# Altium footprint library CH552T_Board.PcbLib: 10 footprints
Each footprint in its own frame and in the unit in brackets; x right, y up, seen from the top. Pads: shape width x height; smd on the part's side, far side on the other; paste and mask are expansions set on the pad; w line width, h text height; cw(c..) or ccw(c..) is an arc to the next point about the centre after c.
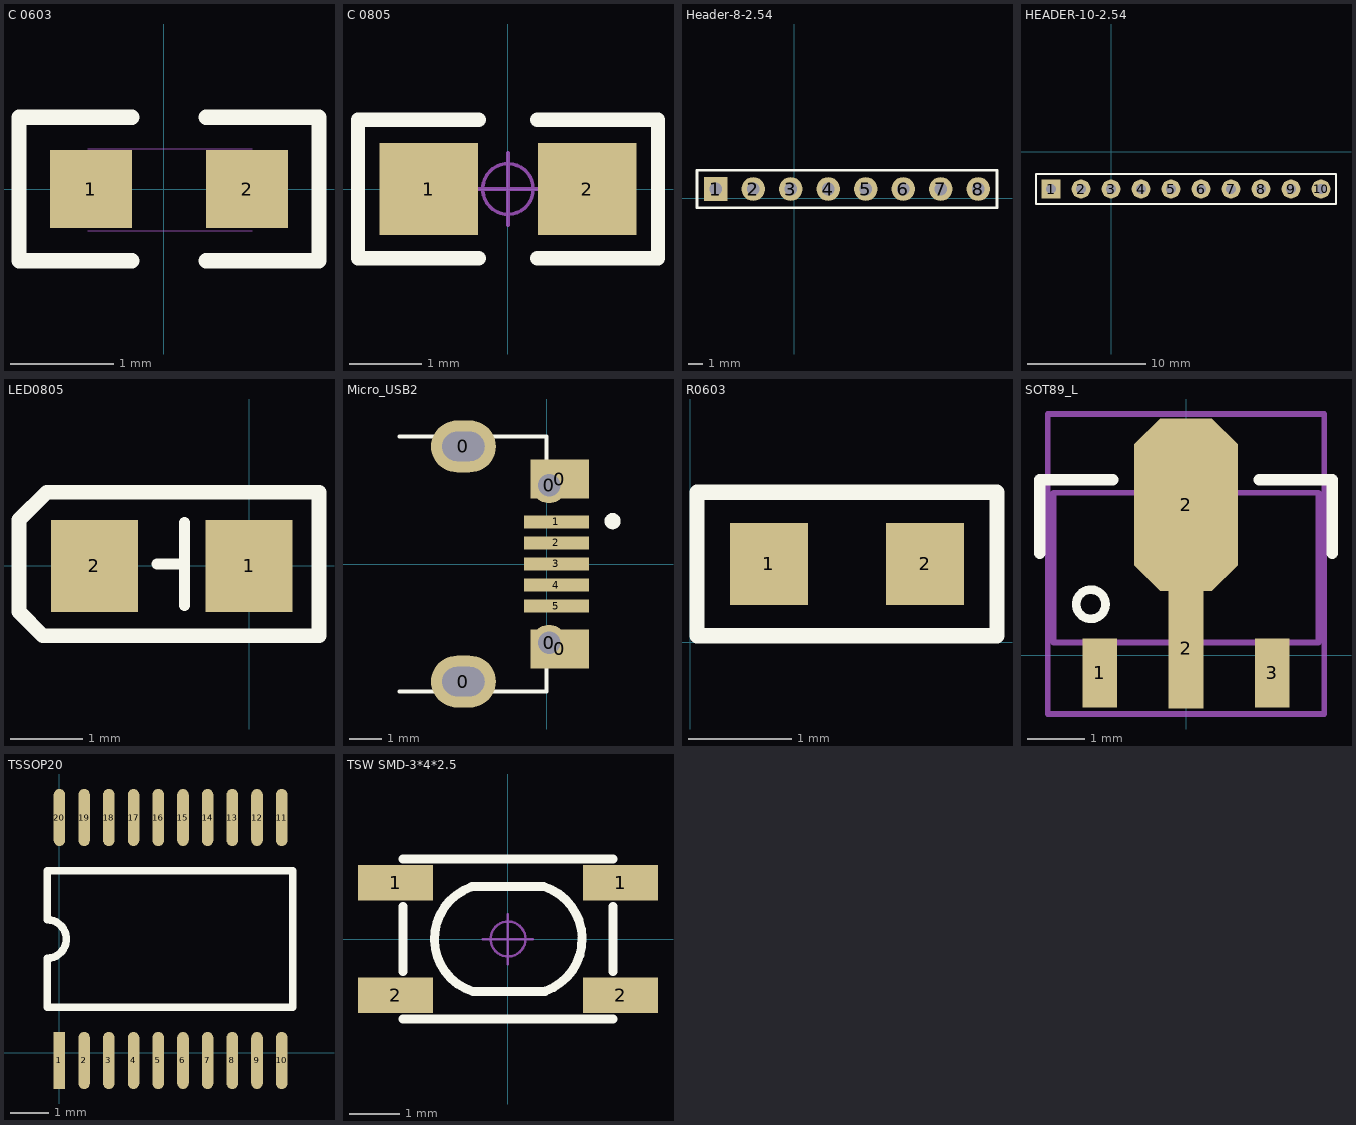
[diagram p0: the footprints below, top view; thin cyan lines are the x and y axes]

## C 0603 [mm] "无极性贴片电容"
pads (2):
  rect 0.8x0.76 smd: 1(-0.711,0) 2(0.809,0)
Top Overlay:
  lines w0.15: -0.311,-0.7 -1.411,-0.7 -1.411,0.7 -0.311,0.7 ; 0.409,-0.7 1.509,-0.7 1.509,0.7 0.409,0.7
Mechanical 13:
  lines w0.01: -0.742,-0.406 0.858,-0.406 ; -0.742,0.394 0.858,0.394
3D body "C 0603.STEP": height 0.81, standoff -0.01, extent -0.742,-0.41 0.858,0.41

## C 0805 [mm] "无极性贴片电容"
height 0.5
pads (2):
  rect 1.36x1.27 smd: 1(-1.094,0) 2(1.094,0)
Top Overlay:
  lines w0.2: -0.406,-0.955 -2.074,-0.955 -2.074,0.955 -0.406,0.955 ; 0.406,-0.955 2.074,-0.955 ; 0.406,0.955 2.074,0.955 ; 2.075,-0.955 2.075,0.955
Mechanical 15:
  circle w0.05: c0,0 r0.35
  lines w0.05: -0.5,0 0.5,0 ; 0,-0.5 0,0.5
3D body "C 0805.STEP": height 0.51, standoff -0.01, extent -1,-0.61 1,0.61

## Header-8-2.54 [mm] "header 8 pin"
pads (8):
  rect 1.6x1.6 hole 0.85: 1(-5.334,0.635)
  round 1.6 hole 0.85: 2(-2.794,0.635) 3(-0.254,0.635) 4(2.286,0.635) 5(4.826,0.635) 6(7.366,0.635) 7(9.906,0.635) 8(12.446,0.635)
Top Overlay:
  lines w0.203: -6.603,-0.635 -6.603,1.905 13.717,1.905 13.717,-0.635 -6.603,-0.635

## HEADER-10-2.54 [mm] "header 10 pin"
pads (10):
  rect 1.6x1.6 hole 0.82: 1(-5.08,-3.175)
  round 1.6 hole 0.85: 2(-2.54,-3.175) 3(0,-3.175) 4(2.54,-3.175) 5(5.08,-3.175) 6(7.62,-3.175) 7(10.16,-3.175) 8(12.7,-3.175) 9(15.24,-3.175) 10(17.78,-3.175)
Top Overlay:
  lines w0.203: -6.35,-4.445 -6.35,-1.905 19.05,-1.905 19.05,-4.445 -6.35,-4.445

## LED0805 [mm]
pads (2):
  rect 1.2x1.27 smd: 1(0,0) 2(-2.134,0)
Top Overlay:
  lines w0.15: -1.273,0.025 -0.892,0.025 ; -0.892,-0.546 -0.892,0.597
  lines w0.203: -3.175,-0.635 -2.845,-0.965 0.965,-0.965 0.965,1.016 -2.794,1.016 -3.175,0.635 -3.175,-0.635

## Micro_USB2 [mm] "Micro_USB Dock 5 Pin"
height 2.65
pads (11):
  oval 2x1.6 hole 0.9 slot 1.3 at 0 deg: 0(-2.564,-3.625) 0(-2.564,3.625)
  round 1.1 hole 0.7: 0(0.08,-2.425) 0(0.08,2.425)
  rect 1.8x1.2 smd: 0(0.4,-2.616) 0(0.4,2.616)
  rect 2x0.4 smd: 1(0.3,1.3) 2(0.3,0.65) 3(0.3,0) 4(0.3,-0.65) 5(0.3,-1.3)
Top Overlay:
  circle w0.25: c2.034,1.321 r0.125
  lines w0.127: -4.539,-3.937 -3.404,-3.937 ; -4.539,3.937 -3.454,3.937 ; -1.727,-3.937 0,-3.937 ; -1.651,3.937 0,3.937 ; 0,-3.9 0,-2.997 ; 0,2.972 0,3.9
3D body "User Library-MicroUSB-B_Molex_105017-0001.STEP": height 2.68, standoff -0.63, extent -5.201,-4.1 0.229,4.1

## R0603 [mm]
pads (2):
  rect 0.76x0.8 smd: 1(0.766,0.762) 2(2.286,0.762)
Top Overlay:
  lines w0.15: 0.066,0.062 0.066,1.462 2.986,1.462 2.986,0.062 0.066,0.062
3D body "RES0603.STEP": height 0.65, standoff 0.2, extent 0.749,0.348 2.349,1.168

## SOT89_L [mm] "4.6x4.3x1.6mm(长宽高)"
height 1.6
pads (4):
  rect 0.6x1.2 smd: 1(-1.5,-0.303) 3(1.5,-0.303)
  rect 0.6x2.1 smd: 2(0,0.127)
  oct 1.8x3 smd: 2(0,2.616)
Top Overlay:
  circle w0.15: c-1.651,0.889 r0.254
  lines w0.2: -2.54,1.778 -2.54,3.048 -1.27,3.048 ; 1.27,3.048 2.54,3.048 2.54,1.778
Mechanical 13:
  circle w0.1: c-1.651,0.889 r0.25
  lines w0.1: -2.3,0.224 -2.3,2.824 2.3,2.824 2.3,0.224 -2.3,0.224
Mechanical 15:
  circle w0.05: c0,1.524 r0.35
  lines w0.05: -0.5,1.524 0.5,1.524 ; 0,1.024 0,2.024
  lines w0.1: -2.4,-1.016 -2.4,4.191 2.4,4.191 2.4,-1.016 -2.4,-1.016
3D body "SOT89.STEP": height 1.6, standoff 0.04, extent -2.314,-0.626 2.286,3.674

## TSSOP20 [mm]
pads (20):
  rect 0.305x1.5 smd: 1(0,-0.2)
  oval 0.305x1.5 smd: 2(0.65,-0.2) 3(1.3,-0.2) 4(1.951,-0.2) 5(2.601,-0.2) 6(3.251,-0.2) 7(3.899,-0.2) 8(4.549,-0.2) 9(5.199,-0.2) 10(5.85,-0.2) 11(5.85,6.194) 12(5.199,6.194) 13(4.549,6.194) 14(3.899,6.194) 15(3.251,6.194) 16(2.601,6.194) 17(1.951,6.194) 18(1.3,6.194) 19(0.65,6.194) 20(0,6.194)
Top Overlay:
  lines w0.2: -0.325,1.2 6.145,1.2 6.145,4.794 -0.325,4.794 -0.325,3.505 cw(c-0.325,2.997) -0.325,2.489 -0.325,1.2

## TSW SMD-3*4*2.5 [mm] "3*4*2.5mm"
height 2.5
pads (4):
  rect 1.5x0.7 smd: 1(-2.25,1.125) 1(2.25,1.125) 2(-2.25,-1.125) 2(2.25,-1.125)
Top Overlay:
  lines w0.178: -2.1,-1.6 2.1,-1.6 ; -2.1,-0.65 -2.1,0.65 ; -2.1,1.6 2.1,1.6 ; -0.738,1.037 ccw(c-0.372,0) -0.7,-1.05 0.737,-1.05 ; -0.725,1.05 0.712,1.05 cw(c0.384,0) 0.75,-1.037 ; 2.1,-0.65 2.1,0.65
Mechanical 15:
  circle w0.05: c0,0 r0.35
  lines w0.05: -0.5,0 0.5,0 ; 0,-0.5 0,0.5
